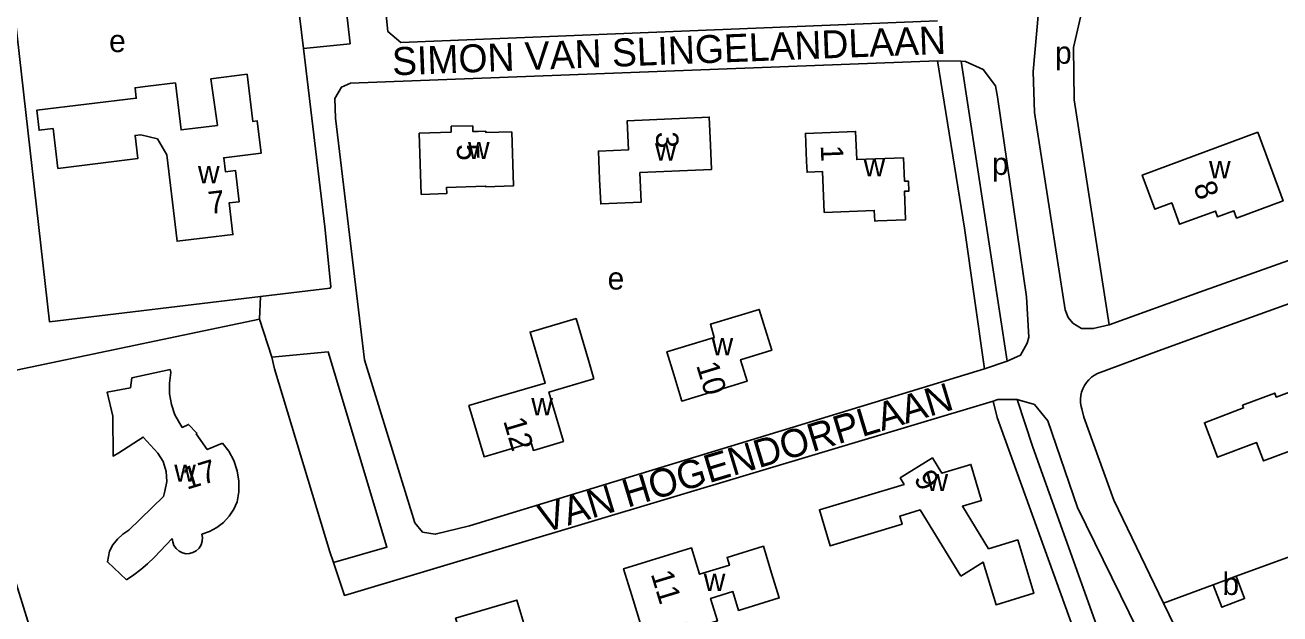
# Model space of a CAD drawing. Extents: x 162427 to 165104, y 384242 to 386287.
# Drawn here: x 163093 to 163317.6, y 385090 to 385195.4 of the extents above; entities that cross this region are included whole.
import ezdxf

# ---------------------------------------------------------------- set-up
doc = ezdxf.new("R2010")
doc.units = 0
for name, color, linetype in [('BLT_Basislijn', 7, 'Continuous'), ('BLT_Bebouwing', 7, 'Continuous'), ('BLT_Centroide', 7, 'Continuous'), ('BLT_Huisnummer', 7, 'Continuous'), ('BLT_Straatnaam', 7, 'Continuous')]:
    doc.layers.add(name, color=color, linetype=linetype)

msp = doc.modelspace()

# ---------------------------------------------------------------- linework, layer by layer
at = {"layer": 'BLT_Basislijn'}
for p, q in [((163147.91, 385220.01), (163151.18, 385192.06)), ((163142.78, 385191.21), (163139.43, 385219.07)), ((163151.18, 385192.06), (163142.78, 385191.21)), ((163260.53, 385188.96), (163256.3, 385189.03)), ((163260.53, 385188.96), (163268.79, 385135.23)), ((163134.95, 385142.77), (163135.11, 385146.8)), ((163134.95, 385142.77), (163137.15, 385135.98)), ((163284.96, 385133.03), (163295.85, 385137.09)), ((163268.79, 385135.23), (163264.73, 385133.89)), ((163282.44, 385125.46), (163282.12, 385126.7)), ((163282.44, 385125.46), (163282.47, 385125.36)), ((163350, 385111.46), (163309.74, 385096.79)), ((163305.66, 385095.24), (163296.76, 385091.97))]:
    msp.add_line(p, q, dxfattribs=at)
for points in [[(163318.27, 385293.27), (163303.64, 385266.9), (163292.63, 385247.23), (163285.11, 385230.66), (163275.67, 385204.1), (163274.41, 385197.77), (163273.42, 385187.12), (163273.67, 385179.73), (163279.17, 385144.44), (163279.67, 385143.09), (163280.53, 385142.07), (163282.1, 385141.12), (163284.19, 385141.07), (163287.03, 385141.75)], [(163326.37, 385291.14), (163303.58, 385250.87), (163298.75, 385242.34), (163295.64, 385235.71), (163293.07, 385229.31), (163282.82, 385200.76), (163280.63, 385191.41), (163280.79, 385182.02), (163287.03, 385141.75)], [(163273.62, 385243.23), (163178.35, 385280.02), (163173.26, 385281.72), (163170.87, 385281.56), (163169.03, 385279.95), (163168.49, 385278.27), (163156.09, 385211.91), (163157.93, 385194.24), (163160.22, 385192.27), (163256.32, 385196.16)], [(163135.11, 385146.8), (163097.33, 385142.31), (163087.26, 385230.97), (163103.3, 385229.91), (163104.85, 385238.23)], [(163135.11, 385146.8), (163147.58, 385148.3), (163147.67, 385148.62), (163146.61, 385159.32), (163142.78, 385191.21)], [(163256.3, 385189.03), (163151.22, 385185.01), (163149.63, 385184.29), (163148.42, 385182.28), (163148.53, 385178.72), (163153.7, 385135.47), (163162.76, 385106.29), (163164.11, 385104.67), (163166.38, 385104.29), (163172.53, 385105.77), (163264.73, 385133.89)], [(163256.3, 385189.03), (163261.12, 385159.08), (163264.73, 385133.89)], [(163260.53, 385188.96), (163261.34, 385188.91), (163264.48, 385187.47), (163266.67, 385184.51), (163267.07, 385182.56), (163272.24, 385146.76), (163272.64, 385139.57), (163272.36, 385138.45), (163271.13, 385136.3), (163268.79, 385135.23)], [(163350, 385164.23), (163303.2, 385147.61), (163287.03, 385141.75)], [(163349.81, 385156.55), (163306.52, 385140.97), (163295.85, 385137.09)], [(163134.95, 385142.77), (163080.24, 385131.33)], [(163137.15, 385135.98), (163147.22, 385136.93), (163157.75, 385101.97), (163148.16, 385099.22)], [(163137.15, 385135.98), (163137.59, 385133.86), (163147.52, 385101.13), (163148.16, 385099.22)], [(163284.96, 385133.03), (163284.39, 385132.73), (163283.86, 385132.36), (163283.38, 385131.93), (163282.96, 385131.44), (163282.6, 385130.9), (163282.31, 385130.32), (163282.09, 385129.72), (163281.95, 385129.08), (163281.88, 385128.44), (163281.9, 385127.79), (163282, 385127.15), (163282.12, 385126.7)], [(163080.24, 385131.33), (163106.15, 385047.69)], [(163148.16, 385099.22), (163150.14, 385093.33), (163266.26, 385128.1)], [(163266.26, 385128.1), (163267.11, 385128.42), (163270.57, 385128.42)], [(163266.26, 385128.1), (163267, 385125.19), (163280.5, 385087.64)], [(163270.57, 385128.42), (163273.66, 385127.47), (163276.05, 385124.56), (163281.39, 385109.07), (163302.9, 385065.15), (163312.18, 385046.3), (163313.27, 385043.5)], [(163270.57, 385128.42), (163273.36, 385119.85), (163290.61, 385071.64), (163302.84, 385050.56), (163308.02, 385041.68), (163309.2, 385041.87), (163313.27, 385043.5)], [(163282.47, 385125.36), (163282.48, 385125.25), (163287.85, 385110.36), (163296.76, 385091.97)], [(163296.76, 385091.97), (163302.95, 385079.18), (163319.54, 385045)]]:
    msp.add_lwpolyline(points, dxfattribs=at)
at = {"layer": 'BLT_Bebouwing'}
msp.add_line((163305.66, 385095.24), (163309.74, 385096.79), dxfattribs=at)
for points in [[(163132.7, 385186.59), (163133.71, 385178.17), (163134.5, 385178.27), (163135.2, 385172.45), (163128.52, 385171.65), (163128.82, 385169.16), (163130.63, 385169.38), (163131.3, 385163.79), (163129.49, 385163.57), (163130.17, 385157.92), (163125.21, 385157.32), (163120.19, 385156.72), (163118.33, 385172.17), (163116.66, 385175.06), (163113.67, 385175.78), (163112.65, 385175.66), (163113.15, 385171.51), (163098.85, 385169.76), (163097.99, 385176.89), (163095.48, 385176.59), (163095.05, 385180.17), (163112.88, 385182.32), (163112.65, 385184.19), (163114.92, 385184.47), (163119.88, 385185.06), (163120.9, 385176.63), (163127.4, 385177.41)], [(163132.7, 385186.59), (163126.24, 385185.81), (163127.4, 385177.41)], [(163173.09, 385177.39), (163169.22, 385177.29)], [(163169.22, 385177.29), (163169.25, 385176.22)], [(163175.45, 385176.43), (163174.08, 385176.38), (163173.13, 385176.34), (163173.09, 385177.39)], [(163215.67, 385173.93), (163215.87, 385169.58), (163203.04, 385169.01), (163203.28, 385163.71), (163196.01, 385163.39), (163195.81, 385167.84), (163195.59, 385172.84), (163201, 385173.08), (163200.77, 385178.27), (163215.45, 385178.92), (163215.67, 385173.93)], [(163169.25, 385176.22), (163163.52, 385176.04), (163163.9, 385165.07)], [(163175.39, 385166.47), (163180.42, 385166.64), (163180.09, 385176.29)], [(163180.09, 385176.29), (163175.47, 385176.16), (163175.45, 385176.43)], [(163245.6, 385160.36), (163250.6, 385160.56), (163250.39, 385165.67), (163251.18, 385165.7), (163251.1, 385167.49), (163250.38, 385167.47), (163250.21, 385171.67), (163241.85, 385171.33), (163241.65, 385176.37), (163232.67, 385176.01), (163232.87, 385171.01), (163232.95, 385169.07), (163235.74, 385169.18), (163236.04, 385161.86), (163244.99, 385162.23), (163245.07, 385160.33), (163245.6, 385160.36)], [(163313.63, 385176.22), (163292.94, 385168.55), (163295.2, 385162.44), (163298.24, 385163.57), (163299.65, 385159.75), (163306.04, 385162.12), (163306.42, 385161.09), (163309.35, 385162.18), (163309.84, 385160.86), (163318.17, 385163.96), (163313.63, 385176.22)], [(163163.9, 385165.07), (163168.45, 385165.23), (163168.41, 385166.34), (163175.39, 385166.58), (163175.39, 385166.47)], [(163225.17, 385141.99), (163226.62, 385137.21), (163221.05, 385135.51), (163222.22, 385131.65), (163210.55, 385128.1), (163209.09, 385132.88), (163207.87, 385136.93), (163216.35, 385139.51), (163215.64, 385141.85), (163224.4, 385144.51), (163225.17, 385141.99)], [(163194.78, 385132.1), (163193.8, 385135.42), (163191.59, 385142.88), (163183.37, 385140.45), (163186.07, 385131.34), (163177.22, 385128.72), (163172.42, 385127.3), (163175.13, 385118.15), (163183.57, 385120.65), (163183.97, 385119.29), (163189.35, 385120.88), (163186.74, 385129.72), (163194.78, 385132.1)], [(163328.15, 385130.11), (163326.39, 385134.79), (163320.75, 385132.67), (163321.55, 385130.56), (163316.94, 385128.82), (163316.68, 385129.53), (163310.9, 385127.36), (163311.09, 385126.87), (163304.09, 385124.24), (163306.42, 385118.05), (163313.41, 385120.68), (163314.64, 385117.41), (163319.32, 385119.17), (163324.94, 385121.28), (163325.9, 385118.72), (163332.45, 385121.18), (163330.64, 385126), (163329.81, 385125.69), (163328.15, 385130.11)], [(163109.72, 385118.87), (163108.71, 385118.27), (163108.65, 385125.39), (163107.69, 385129.72), (163111.81, 385130.5), (163112.05, 385132.26), (163118.93, 385133.75), (163119.03, 385133.22)], [(163119.03, 385133.22), (163118.79, 385131.32), (163118.84, 385129.39), (163119.18, 385127.48), (163119.8, 385125.67)], [(163128.3, 385120.56), (163125.59, 385119.43), (163123.62, 385122.25), (163123.74, 385122.37), (163122.24, 385123.92), (163121.1, 385123.38), (163119.8, 385125.67)], [(163116.72, 385118.78), (163114.13, 385121.66), (163109.72, 385118.87)], [(163117.99, 385111.97), (163118.32, 385113.71), (163118.21, 385115.53), (163117.66, 385117.27), (163116.72, 385118.78)], [(163130.91, 385110.06), (163131.23, 385111.87), (163131.25, 385113.75), (163130.94, 385115.64), (163130.33, 385117.46), (163129.43, 385119.12), (163128.3, 385120.56)], [(163260.49, 385096.77), (163253.17, 385108.62), (163249.54, 385107.53), (163249.97, 385106.07), (163237.09, 385102.2), (163235.16, 385108.65), (163250.33, 385113.2), (163249.62, 385114.35), (163255.39, 385117.93), (163257.05, 385115.23), (163262.27, 385116.78), (163264.19, 385110.34), (163260.75, 385109.3), (163265.44, 385101.68), (163270.67, 385103.26), (163273.54, 385093.71), (163266.79, 385091.67), (163264.5, 385099.25), (163260.49, 385096.77)], [(163117.76, 385111.04), (163117.99, 385111.97)], [(163111.51, 385105.02), (163117.76, 385111.04)], [(163124.62, 385104.28), (163125.99, 385104.75), (163127.3, 385105.46), (163128.49, 385106.38), (163129.51, 385107.49), (163130.32, 385108.74), (163130.91, 385110.06)], [(163111.51, 385105.02), (163110.45, 385104.29), (163109.5, 385103.4), (163108.69, 385102.38), (163108.05, 385101.27)], [(163116.05, 385100.09), (163119.32, 385103.5)], [(163119.32, 385103.5), (163119.39, 385102.89), (163119.62, 385102.27), (163120.01, 385101.7), (163120.54, 385101.24), (163121.16, 385100.93), (163121.81, 385100.8), (163122.42, 385100.82), (163123.01, 385100.98), (163123.6, 385101.29), (163124.11, 385101.76), (163124.48, 385102.36), (163124.69, 385103.02), (163124.73, 385103.68), (163124.62, 385104.28)], [(163111.13, 385096.1), (163107.72, 385099.31), (163108.05, 385101.27)], [(163226.59, 385097.34), (163227.96, 385092.87), (163220.69, 385090.65), (163219.67, 385094.01), (163215.68, 385092.79), (163216.91, 385088.76), (163211.88, 385087.23), (163211.5, 385088.47), (163203.78, 385086.11), (163201.58, 385093.33), (163200.12, 385098.11), (163212.28, 385101.83), (163213.72, 385097.11), (163219.06, 385098.74), (163218.63, 385100.14), (163225.13, 385102.12), (163226.59, 385097.34)], [(163111.13, 385096.1), (163112.42, 385097.01), (163113.68, 385097.99), (163114.89, 385099.01), (163116.05, 385100.09)], [(163309.74, 385096.79), (163311.27, 385092.75), (163307.19, 385091.2), (163305.66, 385095.24)], [(163170.47, 385087.74), (163170.03, 385089.24), (163180.98, 385092.5), (163182.4, 385087.71)]]:
    msp.add_lwpolyline(points, dxfattribs=at)

# ---------------------------------------------------------------- texts
at = {"layer": 'BLT_Centroide'}
for s, p in [('e', (163108.01, 385190.57)), ('p', (163277.35, 385188.48)), ('w', (163172.26, 385171.41)), ('w', (163205.73, 385171.16)), ('w', (163243.06, 385168.34)), ('p', (163266.06, 385168.58)), ('w', (163304.91, 385168)), ('w', (163123.92, 385167.08)), ('e', (163197.25, 385148.07)), ('w', (163215.86, 385136.31)), ('w', (163183.59, 385125.56)), ('w', (163119.67, 385113.67)), ('w', (163254.34, 385112)), ('w', (163214.46, 385094.12)), ('b', (163307.32, 385093.4))]:
    msp.add_text(s, height=4, dxfattribs=at).set_placement(p)
at = {"layer": 'BLT_Huisnummer'}
for s, rotation, p in [('3', 272.5345, (163205.87, 385176.26)), ('5', 272.5468, (163170.21, 385174.05)), ('1', 272.3273, (163235.39, 385173.86)), ('7', 6.8703, (163125.98, 385161.57)), ('8', 290.3427, (163302.04, 385166.6)), ('10', 286.9056, (163213.07, 385134.52)), ('12', 286.4766, (163178.53, 385124.58)), ('17', 16.9538, (163121.91, 385112.22)), ('9', 302.1155, (163251.93, 385114.2)), ('11', 286.9939, (163204.94, 385097.18))]:
    msp.add_text(s, height=4, rotation=rotation, dxfattribs=at).set_placement(p)
at = {"layer": 'BLT_Straatnaam'}
for s, rotation, p in [('SIMON VAN SLINGELANDLAAN', 2.2457, (163158.76, 385186.39)), ('VAN HOGENDORPLAAN', 16.7777, (163185.86, 385104.49))]:
    msp.add_text(s, height=5, rotation=rotation, dxfattribs=at).set_placement(p)

doc.saveas('drawing.dxf')
